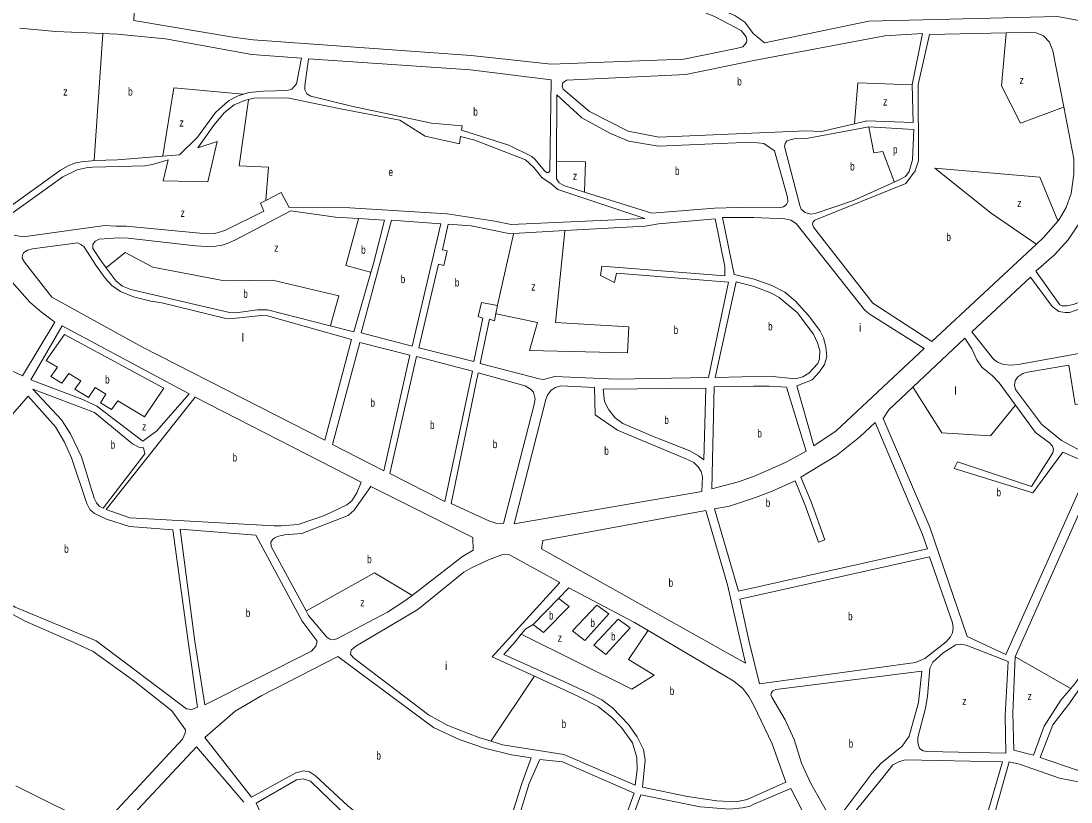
# Model space of a CAD drawing. Extents: x 639657 to 671642, y 222838 to 252123.
# Drawn here: x 647091 to 648393, y 241801 to 242770 of the extents above; entities that cross this region are included whole.
import ezdxf

# ---------------------------------------------------------------- set-up
doc = ezdxf.new("R2010")
doc.units = 0
doc.header["$LTSCALE"] = 4
doc.layers.add('1', color=7, linetype='Continuous', lineweight=13)
doc.layers.add('21', color=7, linetype='Continuous', lineweight=13)
doc.layers.add('7', color=7, linetype='Continuous')

msp = doc.modelspace()

# ---------------------------------------------------------------- linework, layer by layer
at = {"layer": '1'}
for p, q in [((647134.57, 242756.69), (647090.209, 242760.748)), ((648339.65, 242755.58), (648312.78, 242754.994)), ((647699.28, 242517.39), (647864.7, 242524.83))]:
    msp.add_line(p, q, dxfattribs=at)
for points in [[(648475.98, 242756.77), (648376.31, 242775.21), (648142.52, 242769.48), (648013.13, 242742.54), (647999.2, 242754.16), (647988.99, 242768.22), (647976.55, 242776.66), (647885.12, 242815.13), (647816.64, 242839.95), (648199.3, 242913.73), (648230.16, 242918.09), (648262.57, 242919.67), (648282.75, 242919.08), (648368, 242913.27), (648382.38, 242915.24), (648400.83, 242922.59)], [(647367.385, 242679.215), (647373.95, 242681.34), (647392.01, 242682.98), (647421.67, 242683.5), (647427.27, 242685.2), (647432.88, 242691.84), (647439.01, 242723.62), (647377.77, 242728.18), (647270.59, 242747.54), (647210.86, 242753.59), (647193.101, 242754.312), (647134.57, 242756.69)], [(648064.94, 242633.79), (647882.07, 242625.57), (647844.05, 242633.27), (647796.43, 242657.56), (647763.43, 242685.22), (647762.15, 242688.88), (647763.03, 242693.18), (647767.77, 242696.38), (647915.46, 242703.44), (647999.87, 242720.81), (648162.53, 242751.49), (648208.9, 242754.18), (648196.4, 242690.59)], [(648312.78, 242754.994), (648217.71, 242752.92), (648203.49, 242691.25), (648204.16, 242596.56), (648200.12, 242583.88), (648188.35, 242568.18), (648075.53, 242522.81), (648073.61, 242520.66), (648072.76, 242517.87), (648074.05, 242514), (648147.52, 242419.72), (648220.43, 242372.45), (648350.264, 242493.088)], [(648384.189, 242663.305), (648370.84, 242732.89), (648366.52, 242743.4), (648359.2, 242751.33), (648349.96, 242755.17), (648339.65, 242755.58)], [(647267.409, 242602.008), (647288.12, 242603.66), (647310.13, 242625.93), (647332.59, 242656.36), (647348.76, 242670.69), (647360.82, 242677.09), (647367.385, 242679.215)], [(648196.4, 242690.59), (648197.6, 242643.78), (648140.05, 242646), (648124.819, 242642.402)], [(647373.459, 242672.493), (647369.62, 242671.47), (647355.84, 242665.94), (647343.55, 242656.31), (647330.6, 242640.68), (647310.51, 242612.38), (647334.82, 242620.24), (647323.03, 242570.41), (647267.58, 242571.71), (647273.7, 242597.7), (647254.33, 242591.76), (647244.87, 242590.29), (647180.39, 242588.62), (647172.43, 242587.79), (647161.03, 242585.04), (647143.16, 242576.73), (647072.9, 242526.05)], [(647485.43, 242661.3), (647421.86, 242674.69), (647379.94, 242674.22), (647373.459, 242672.493)], [(647755.352, 242596.018), (647755.66, 242678.17), (647786.72, 242649.87), (647822.33, 242630.14), (647845.08, 242620.79), (647881.59, 242614.61), (647996.61, 242619.68), (648012.16, 242617.77), (648025.5, 242609), (648041.54, 242551.5), (648041.98, 242545.49), (648040.49, 242542.26), (648036.84, 242539.46), (648030.41, 242538.16)], [(647864.7, 242524.83), (647756.94, 242560.79), (647748.8, 242567.71), (647737.01, 242575.72), (647727.38, 242588.23), (647716.89, 242597.52), (647654.22, 242622.09), (647636.18, 242626.68), (647635.07, 242617.44), (647592.55, 242626.87), (647561.03, 242647), (647485.43, 242661.3)], [(648376.88, 242521.691), (648378.69, 242523.77), (648387.03, 242538.61), (648393.42, 242555.8), (648396.58, 242579.86), (648396.53, 242598.97), (648384.189, 242663.305)], [(648124.819, 242642.402), (648084.05, 242632.77), (648064.94, 242633.79)], [(648142.43, 242638.71), (648065.39, 242623.92), (648050.15, 242623.88), (648040.92, 242621.07), (648039, 242618.06), (648038.15, 242614.19), (648056.81, 242541.02), (648058.75, 242536.3), (648063.7, 242532.23), (648070.79, 242530.31), (648075.94, 242531.19), (648123.56, 242547.19), (648173.971, 242570.144)], [(648196.65, 242597.83), (648198.48, 242635.41), (648142.43, 242638.71)], [(647182.005, 242596.665), (647211.15, 242597.52), (647267.409, 242602.008)], [(647053.315, 242546.77), (647055.77, 242543.32), (647069.27, 242533.38), (647140.39, 242584.69), (647149.87, 242590.24), (647157.62, 242593.44), (647166.44, 242595.34), (647179.13, 242596.58), (647182.005, 242596.665)], [(647789.901, 242557.716), (647764.48, 242565.7), (647758.48, 242569.17), (647755.27, 242574.13), (647755.352, 242596.018)], [(648173.971, 242570.144), (648181.89, 242573.75), (648187.9, 242576.98), (648192.6, 242583), (648196.65, 242597.83)], [(647394.93, 242547.195), (647413.89, 242557.13), (647423.92, 242538.39), (647499.15, 242538.28), (647619.91, 242530.66), (647678.76, 242521.59), (647699.28, 242517.39)], [(648030.41, 242538.16), (647979.74, 242538.7), (647951.36, 242537.54), (647873.53, 242531.45), (647789.901, 242557.716)], [(647083.13, 242504.08), (647094.3, 242502.1), (647195.58, 242516.11), (647208.91, 242515.19), (647222.02, 242515.57), (647321.71, 242505.92), (647331.59, 242506.31), (647344.07, 242510.13), (647392.31, 242534.01), (647388.26, 242543.7), (647394.93, 242547.195)], [(647510.022, 242524.91), (647481.48, 242526.75), (647425.84, 242534.3), (647356.49, 242498.04), (647347.23, 242493.78), (647340.78, 242491.87), (647332.82, 242490.61), (647322.07, 242490.23), (647307.68, 242491.15), (647224.32, 242500.3), (647212.72, 242500.78), (647188.43, 242499.15), (647183.47, 242496.81), (647180.66, 242492.73), (647180.64, 242487.58), (647191.11, 242471.62), (647196.943, 242463.729)], [(647527.88, 242467.43), (647542.29, 242522.83), (647510.022, 242524.91)], [(647680.101, 242406.972), (647678.27, 242398.19), (647672.26, 242399.94), (647660.85, 242345.16), (647733.85, 242325.92), (647739, 242325.25), (647753.2, 242329.05), (647829.49, 242325.48), (647943.62, 242327.75), (647968.41, 242446.09), (647829.61, 242457.27), (647827.19, 242445.68), (647810.03, 242454.14), (647811.37, 242465.74), (647964.14, 242453.85), (647964.19, 242465.46), (647951.96, 242524.64), (647881.65, 242518.3), (647865.09, 242515.59)], [(647698.17, 242505.88), (647649.51, 242515.7), (647621.15, 242517.76), (647614.15, 242486.19), (647619.73, 242484.66), (647615.57, 242466.62), (647608.92, 242468.15), (647584.85, 242364.63), (647652.7, 242347.56), (647664.1, 242401.48), (647658.3, 242403.22), (647662.24, 242420.83), (647682.21, 242417.09), (647680.101, 242406.972)], [(647698.17, 242505.88), (647702.072, 242506.107), (647765.857, 242509.818), (647865.09, 242515.59)], [(648350.264, 242493.088), (648359.21, 242501.4), (648376.88, 242521.691)], [(648761.04, 242453.22), (648759.63, 242498.73), (648652.51, 242495.04), (648544.39, 242462.35), (648391.23, 242408.3), (648386.08, 242408.28), (648378.13, 242409.55), (648369.74, 242415.97), (648342.81, 242452.19), (648270.21, 242384.17), (648297.13, 242350.53), (648301.87, 242346.68), (648309.6, 242343.9), (648318.84, 242343.07), (648327.64, 242343.95), (648462.19, 242368.11), (648485.81, 242369.46), (648514.57, 242369.53), (648535.83, 242367.65), (648547.304, 242365.892), (648673.204, 242346.603)], [(647005.043, 242370.874), (647093.18, 242329.89), (647133.21, 242396.17), (647116.71, 242408.71), (647102.36, 242421.02), (647080.54, 242446.04), (647064.011, 242474.655)], [(647196.943, 242463.729), (647209.28, 242447.04), (647217.43, 242440.99), (647227.72, 242436.65), (647350.12, 242408.41), (647357.64, 242407.95), (647384.52, 242411.49), (647397.2, 242411.44), (647474.84, 242391.907)], [(647474.84, 242391.907), (647504.12, 242384.54), (647525.2, 242458.079), (647527.88, 242467.43)], [(648324.41, 242293.388), (648304.08, 242320.92), (648295.9, 242329.7), (648282.77, 242340.62), (648276.31, 242349.62), (648270.26, 242363.34), (648261.42, 242376.42), (648197.271, 242315.764)], [(648390.541, 242342.903), (648339.26, 242334.32), (648333.25, 242332.59), (648327.25, 242328.71), (648324.04, 242323.55), (648323.2, 242318.18), (648324.5, 242313.03), (648356.6, 242269.96), (648381.35, 242249.63), (648434.299, 242221.396)], [(648390.541, 242342.903), (648398.521, 242294.274), (648413.2, 242296.372), (648404.192, 242345.188)], [(648197.271, 242315.764), (648167.4, 242287.52), (648160.13, 242276.77), (648218.24, 242142.1), (648264.25, 242006.58)], [(648264.25, 242006.58), (648312.32, 241984.39), (648412.59, 242208.92), (648407.82, 242224.58), (648382.89, 242235.25), (648345.88, 242184.49), (648248.32, 242214.95), (648252.38, 242223.33), (648344.35, 242192.43), (648370.65, 242234.36), (648371.29, 242238.87), (648370.2, 242242.51), (648366.97, 242246.37), (648349.33, 242259.64), (648324.41, 242293.388)], [(648398.97, 241949.45), (648442.64, 242013.16), (648498.51, 242112.54), (648490.22, 242162.1), (648485.03, 242173.68), (648463.52, 242191.44), (648437.5, 242207.48), (648431.48, 242209.39), (648418.21, 242193.05), (648324.1, 241981.38)], [(647576.308, 242057.511), (647638.95, 242105.72), (647652.1, 242113.4), (647651.74, 242129.32), (647525.22, 242192.44), (647504.67, 242163.28), (647497.12, 242156.43), (647439.64, 242134.31), (647418.14, 242132.47), (647409.32, 242130.35), (647406.09, 242128.86)], [(647406.09, 242128.86), (647403.72, 242127.15), (647401.34, 242123.72), (647401.74, 242118.34), (647444.93, 242038.208)], [(647500.81, 241989.47), (647506.43, 241994.43), (647583.42, 242039.94), (647640.37, 242086.14), (647649.2, 242091.26), (647670.96, 242101.7), (647687.75, 242107.65), (647696.13, 242108.04), (647702.57, 242105.01), (647759.59, 242073.57), (647675.41, 241981.36), (647727.859, 241957.32)], [(647757.985, 242053.719), (647770.73, 242066.85), (647852.17, 242023.73), (647868.882, 242013.866)], [(647444.93, 242038.208), (647447.98, 242032.55), (647470.64, 242005.58), (647474.28, 242003.2), (647477.93, 242002.32), (647483.09, 242003.59), (647545.79, 242036.87), (647568.64, 242051.61), (647576.308, 242057.511)], [(647711.654, 242009.265), (647717.2, 242016.12), (647726.46, 242021.24), (647757.985, 242053.719)], [(647053.91, 242048.11), (647096.79, 242025.58), (647156.14, 241999.7), (647180.89, 241987.99), (647232.37, 241950.63), (647278.49, 241914.32), (647295.34, 241890.77), (647294.93, 241886.48), (647291.74, 241879.17), (647189.6, 241769.28), (647085.01, 241821.24)], [(648039.64, 241825.94), (647991.6, 241804.41), (647978.08, 241801.56), (647954.03, 241802.76), (647917.72, 241808.2), (647862.07, 241819.58), (647865.14, 241853.08), (647863.15, 241866.38), (647855.35, 241882.24), (647844.54, 241897.44), (647824.91, 241918.19), (647811.56, 241928.01), (647797.14, 241935.25), (647768.31, 241949.09), (647690.21, 241984.42), (647704.1, 241999.93), (647711.654, 242009.265)], [(647868.882, 242013.866), (647963.87, 241957.8), (647975.06, 241950.97), (647986.27, 241942), (647993.83, 241931.94), (647999.89, 241920.8), (648022.78, 241873.63), (648039.64, 241825.94)], [(647674.183, 241876.769), (647659.11, 241881.47), (647620.61, 241896.13), (647596.72, 241909.56), (647503.64, 241980.04), (647499.97, 241984.75), (647500.81, 241989.47)], [(648324.1, 241981.38), (648321.15, 241912.05), (648322.34, 241865.47), (648346.81, 241859.41), (648359.99, 241895.23), (648380.45, 241927.59), (648392.808, 241942.177), (648398.97, 241949.45)], [(647727.859, 241957.32), (647780.83, 241933.04), (647806.87, 241919.62), (647824.11, 241906.16), (647835.76, 241893.75), (647849.37, 241874.7), (647855.03, 241856.69), (647855.53, 241841.02), (647852.82, 241822.33), (647764.41, 241860.2), (647688.35, 241872.35), (647674.183, 241876.769)], [(647367.55, 241801.031), (647308.96, 241869.79), (647206.39, 241760.11), (647307.32, 241707.06), (647336.119, 241696.742)]]:
    msp.add_lwpolyline(points, dxfattribs=at)
for points in [[(647991.27, 242745.85), (647990.43, 242750.15), (647984.44, 242757.92), (647951.4, 242775.27), (647857.39, 242813.32), (647829.91, 242822.26), (647802.2, 242827.98), (647778.35, 242829.59), (647749.54, 242829.72), (647720.73, 242826.63), (647623.35, 242824.27), (647489.24, 242826.15), (647327.61, 242826.83), (647275.61, 242830.7), (647234.15, 242838.39), (647231.34, 242770.49), (647354.21, 242749.56), (647379.34, 242746.66), (647649.45, 242727.01), (647748.71, 242716.24), (647913.16, 242722.58), (647978.12, 242735.6), (647986.51, 242737.92), (647990.83, 242743.06)], [(647501.13, 242664.03), (647450.88, 242676.71), (647445.95, 242679.53), (647443.17, 242684.27), (647443.19, 242689.43), (647447.82, 242722.73), (647648.52, 242709.39), (647748.64, 242696.9), (647746.93, 242584.06), (647745.42, 242582.13), (647743.05, 242582.14), (647740.48, 242584.08), (647728.93, 242598.11), (647724.64, 242601.78), (647696.32, 242615.88), (647637.5, 242634.63), (647638.38, 242639.79), (647600.35, 242643.18)], [(648480.354, 242638.657), (648556.16, 242636.72), (648558.96, 242635.44), (648560.68, 242633.08), (648602.02, 242506.72), (648604.63, 242495.13), (648600.14, 242489.32), (648596.49, 242487.17), (648525.32, 242464.75), (648395.72, 242418.4), (648388.21, 242416.45), (648382.41, 242416.65), (648379.4, 242417.93), (648349.66, 242459.51), (648372.8, 242479.96), (648389.49, 242498.25), (648403.82, 242519.54), (648412.14, 242539.53), (648420.02, 242564.67), (648421.71, 242575.62)], [(647611.91, 242518.23), (647550.67, 242522.8), (647513.14, 242383), (647576.48, 242366.6)], [(648022.28, 242441.74), (648000.58, 242449.84), (647975.75, 242455.3), (647961.21, 242526.31), (648000.11, 242526.13), (648038.39, 242524.65), (648045.69, 242522.74), (648052.36, 242518.67), (648137.02, 242411.75), (648143.04, 242406.61), (648211.22, 242363.63), (648102.2, 242261.38), (648074.34, 242242.85), (648053.31, 242317.51), (648072.19, 242324.85), (648081.4, 242334.54), (648087.6, 242344), (648090.58, 242353.24), (648089.26, 242365.69), (648086.44, 242376.84), (648081.9, 242386.06), (648067.9, 242404.71), (648051.11, 242422.7), (648038.2, 242433.4)], [(647468.3, 242249.88), (647501.29, 242374.67), (647396.95, 242404.35), (647389.65, 242404.81), (647350.08, 242400.46), (647343.64, 242401.34), (647266.13, 242420.37), (647252.38, 242422.57), (647230.91, 242427.82), (647214.82, 242434.33), (647204.1, 242441.9), (647195.76, 242450.75), (647185.07, 242465.63), (647169.48, 242489.98), (647165.83, 242492.79), (647161.97, 242494.53), (647105.85, 242487.44), (647099.39, 242485.53), (647095.08, 242482.75), (647093.14, 242479.97), (647092.69, 242475.88), (647095.9, 242470.71), (647129.68, 242427.36), (647242.26, 242365.21)], [(648021.88, 242432.29), (648000.249, 242440.664), (647978.08, 242446.48), (647952.01, 242327.71), (648018.88, 242329.2), (648051.79, 242325.88), (648060.58, 242328.47), (648068.09, 242333.22), (648079.22, 242345.27), (648081.35, 242350.85), (648081.75, 242361.16), (648078.94, 242370.81), (648073.97, 242381.54), (648053.5, 242408.32), (648031.56, 242426.73)], [(647300.05, 242307.35), (647142.65, 242391.62), (647103.69, 242324.69), (647168.28, 242300.35), (647185.44, 242292.33), (647242.63, 242248.88), (647259.88, 242261.49)], [(647573.64, 242355.43), (647511.59, 242370.97), (647477.52, 242244.68), (647541.21, 242211.94)], [(647651.14, 242335.53), (647581.58, 242353.89), (647548.51, 242208.68), (647616.7, 242173.98)], [(647716.61, 242317.18), (647658.22, 242333.56), (647624.85, 242171.58), (647671.39, 242150.09), (647680.19, 242147.25), (647689.43, 242146.78), (647727.26, 242292.4), (647729.01, 242301.21), (647726.9, 242309.61), (647723.05, 242313.28)], [(647803.29, 242281.31), (647802.58, 242315.28), (647760.68, 242317.41), (647754.22, 242315.5), (647748.62, 242311.87), (647744.29, 242305.87), (647742.12, 242300.29), (647702.75, 242146.29), (647935.7, 242186.52), (647936.21, 242204.58), (647934.73, 242211.25), (647931.11, 242217.08), (647925.54, 242222.26), (647915.03, 242227.47), (647830.93, 242262.26)], [(647937.81, 242225.43), (647940.34, 242314.65), (647813.1, 242313.09), (647814.97, 242298.03), (647820.08, 242287.47), (647827.99, 242277.54), (647837.63, 242270.62), (647874.32, 242254.97), (647920.66, 242236.69), (647931.17, 242230.62)], [(648018.96, 242316.78), (647999.46, 242317.17), (647950.67, 242316.11), (647947.75, 242189.69), (647981.1, 242198.35), (648001.45, 242205.73), (648040.03, 242222.8), (648064.69, 242236.17), (648040.65, 242315.54)], [(647310.46, 241918.95), (647298.5, 242000.26), (647279.76, 242138.84), (647226.05, 242143.14), (647197.29, 242152.07), (647182.5, 242159.01), (647176.93, 242164.2), (647173.09, 242171.31), (647154, 242227.94), (647145.27, 242247.54), (647134.18, 242266.73), (647100.38, 242304.49), (646967.34, 242152.1), (646991.09, 242129.22), (647017.81, 242096), (647061.68, 242056.47), (647084.4, 242042.83), (647184.75, 242001.31), (647296.73, 241916.75), (647303.17, 241916.13)], [(647182.39, 242284.17), (647106.01, 242313.28), (647141.52, 242275.3), (647152.62, 242258.05), (647166.47, 242229.4), (647182.15, 242178.15), (647184.92, 242172.12), (647188.55, 242168.02), (647193.49, 242165.64), (647244.93, 242233.17), (647243.24, 242240.7), (647237.66, 242241.15), (647229.72, 242245.27)], [(647513.21, 242198.08), (647307.56, 242303.45), (647196.92, 242164.12), (647226.53, 242153.89), (647234.05, 242153.22), (647405.29, 242143.7), (647414.11, 242143.66), (647434.96, 242145.51), (647467.89, 242156.56), (647495.46, 242169.77), (647501.5, 242174.91), (647507.99, 242184.77)], [(648022.52, 242186.91), (648002.03, 242179.07), (647970, 242168.3), (647951.29, 242164.73), (647980.92, 242062.93), (648215.09, 242115.05), (648209.03, 242132.85), (648150.27, 242271.81), (648131.42, 242254.16), (648102.28, 242230.9), (648058.12, 242204.17), (648070.87, 242173.72), (648087.95, 242126.54), (648080.23, 242123.51), (648063.36, 242170.05), (648051.26, 242199.65)], [(647967.19, 242070.68), (647989.8, 241973.51), (647736.57, 242115.39), (647738.55, 242125.71), (647940.53, 242162.85)], [(647456.77, 241994.67), (647458.567, 242000.923), (647440, 242025.71), (647382.46, 242132.18), (647288.79, 242139.66), (647306.87, 242000.3), (647319.25, 241921.78), (647451.65, 241988.2)], [(648538.87, 242000), (648581.7, 242074.75), (648506.46, 242110.2), (648471.4, 242051.3), (648451.98, 242012.2), (648391.62, 241924.35), (648370.73, 241897.13), (648354.75, 241856.6), (648400.68, 241840.83), (648428.59, 241840.77), (648447.5, 241843.95)], [(648211.77, 241979.05), (648238.359, 242000.01), (648243.72, 242006.3), (648246.07, 242011.24), (648246.91, 242017.47), (648246.46, 242023.48), (648217.91, 242105.4), (647982.56, 242052.75), (647994.15, 242000.02), (648006.81, 241948.03), (648200.59, 241974.35)], [(648215.017, 241863.991), (648312.24, 241861.84), (648311.7, 241908.64), (648315.06, 241975.6), (648263.13, 241995.68), (648256.26, 241996.98), (648250.24, 241996.13), (648234.55, 241986.3), (648221.85, 241974.73), (648218.19, 241967.44), (648215.32, 241932.03), (648212.93, 241917.87), (648203.19, 241881.19), (648203.17, 241874.53), (648205.52, 241867.66), (648210.03, 241864.86)], [(647389.84, 241933.22), (647484.31, 241981.89), (647602.8, 241893.7), (647634.86, 241879.01), (647666.04, 241867.97), (647699.57, 241859.73), (647724.06, 241856.18), (647712.18, 241824.14), (647694.82, 241769.33), (647678.61, 241742.86), (647667.28, 241732.73), (647653.78, 241726.88), (647634.67, 241725.94), (647585.88, 241737.35), (647520.44, 241777.02), (647496.52, 241796.46), (647456.63, 241833.88), (647449.09, 241838.78), (647441.79, 241839.83), (647432.35, 241837.43), (647377.31, 241807.16), (647319.43, 241881.42), (647356.86, 241913.77)], [(648204.14, 241924.76), (648208.08, 241963.6), (648027.43, 241940.81), (648023.35, 241939.11), (648021.84, 241937.18), (648020.97, 241934.39), (648022.26, 241931.17), (648038.95, 241903.22), (648050.06, 241878.73), (648059.24, 241849.51), (648070.35, 241825.23), (648099.02, 241773.85), (648146.4, 241836.66), (648158.02, 241849.3), (648184.05, 241870.49), (648192.45, 241883.14)], [(647721.41, 241824.18), (647734.517, 241854.174), (647762.73, 241851.18), (647851.79, 241812.24), (647803.85, 241679.8), (647751.82, 241695.27), (647673.34, 241722.45), (647688.93, 241741.4), (647703.21, 241765.28)], [(648159.92, 241831.69), (648105.44, 241764.82), (648174.41, 241677.5), (648203.14, 241653.39), (648290.62, 241789.98), (648308.35, 241851.12), (648187.88, 241853.74), (648180.36, 241851.61), (648172.41, 241847.33)], [(648569.43, 241715.31), (648594.07, 241794.04), (648469.37, 241827.8), (648450.26, 241828.7), (648420.19, 241825.12), (648404.51, 241826.01), (648378.97, 241830.79), (648329.18, 241848.07), (648316.3, 241851.1), (648298.99, 241789.53)], [(647513.81, 241769.7), (647557.09, 241743.25), (647476.78, 241646.54), (647419.79, 241667.57), (647423.74, 241696.78), (647419.99, 241718.66), (647382.92, 241799.67), (647433.04, 241828.63), (647441.4, 241830.17), (647450.22, 241827.2), (647486.88, 241792.13)], [(647999.78, 241798.43), (648045.64, 241817.98), (648066.17, 241778.86), (648069.38, 241770.48), (648070.65, 241762.75), (648067.4, 241750.73), (648050.14, 241712.55), (647924.77, 241669.97), (647909.96, 241667.76), (647832.43, 241673.9), (647812.01, 241678.33), (647859.74, 241810.34), (647933.24, 241795.38), (647969.75, 241792.3), (647986.06, 241794.08), (647995.28, 241796.05)]]:
    msp.add_lwpolyline(points, close=True, dxfattribs=at)
at = {"layer": '21'}
for points in [[(647193.101, 242754.312), (647193.066, 242753.812), (647182.04, 242597.164), (647182.005, 242596.665)], [(648312.78, 242754.994), (648312.736, 242754.494), (648306.951, 242689.4), (648330.718, 242643.244), (648383.689, 242663.117), (648384.189, 242663.305)], [(648124.819, 242642.402), (648124.861, 242642.902), (648129.054, 242693.244), (648195.9, 242690.61), (648196.4, 242690.59)], [(647267.409, 242602.008), (647267.488, 242602.508), (647280.815, 242686.95), (647366.885, 242679.26), (647367.385, 242679.215)], [(647373.459, 242672.493), (647373.389, 242671.993), (647361.9, 242590.094), (647398.248, 242588.695), (647394.97, 242547.695), (647394.93, 242547.195)], [(648142.43, 242638.71), (648142.526, 242638.21), (648148.626, 242606.526), (648159.81, 242607.925), (648173.784, 242570.644), (648173.971, 242570.144)], [(647755.352, 242596.018), (647755.852, 242596.009), (647791.436, 242595.337), (647789.921, 242558.216), (647789.901, 242557.716)], [(648350.264, 242493.088), (648349.764, 242493.43), (648294.369, 242531.35), (648224.469, 242587.297), (648354.484, 242576.107), (648376.674, 242522.191), (648376.88, 242521.691)], [(647510.022, 242524.91), (647509.885, 242524.41), (647494.011, 242466.659), (647524.7, 242458.217), (647525.2, 242458.079)], [(647680.101, 242406.972), (647680.601, 242406.866), (647731.672, 242396.027), (647721.886, 242361.06), (647843.512, 242358.263), (647844.91, 242390.432), (647754.04, 242396.027), (647765.805, 242509.317), (647765.857, 242509.818)], [(647682.21, 242417.09), (647682.322, 242417.59), (647701.96, 242505.607), (647702.072, 242506.107)], [(647196.943, 242463.729), (647197.443, 242464.129), (647220.701, 242482.744), (647254.952, 242464.561), (647343.725, 242447.777), (647403.141, 242448.477), (647485.623, 242428.895), (647474.986, 242392.407), (647474.84, 242391.907)], [(648324.41, 242293.388), (648324, 242292.888), (648293.323, 242255.459), (648233.209, 242258.956), (648197.587, 242315.264), (648197.271, 242315.764)], [(647576.308, 242057.511), (647575.808, 242057.813), (647529.669, 242085.684), (647445.43, 242038.488), (647444.93, 242038.208)], [(647726.46, 242021.24), (647726.96, 242020.854), (647739.33, 242011.307), (647771.072, 242043.9), (647758.485, 242053.344), (647757.985, 242053.719)], [(647711.654, 242009.265), (647712.154, 242009.016), (647848.755, 241941.108), (647876.32, 241958.658), (647844.579, 241977.879), (647868.544, 242013.366), (647868.882, 242013.866)], [(648324.1, 241981.38), (648324.6, 241981.095), (648392.308, 241942.462), (648392.808, 241942.177)], [(647727.859, 241957.32), (647727.526, 241956.82), (647674.516, 241877.269), (647674.183, 241876.769)]]:
    msp.add_lwpolyline(points, dxfattribs=at)
for points in [[(647145.2, 242381.169), (647268.637, 242314.671), (647244.413, 242278.736), (647211.418, 242298.793), (647203.483, 242287.929), (647190.118, 242296.286), (647196.8, 242307.15), (647183.435, 242315.507), (647175.082, 242302.972), (647158.376, 242313.418), (647165.476, 242323.447), (647150.858, 242332.639), (647142.088, 242320.522), (647128.305, 242328.879), (647136.658, 242340.578), (647122.458, 242348.935)], [(647805.367, 242045.48), (647775.248, 242013.397), (647790.283, 242001.697), (647820.354, 242034.707)], [(647831.679, 242027.93), (647801.56, 241995.847), (647816.595, 241984.147), (647846.666, 242017.157)]]:
    msp.add_lwpolyline(points, close=True, dxfattribs=at)

# ---------------------------------------------------------------- texts
at = {"layer": '7'}
for s, width, p in [('b', 0.75, (647979.386, 242689.875)), ('z', 0.8, (648329.302, 242691.527)), ('z', 0.8, (647143.891, 242677.292)), ('b', 0.75, (647224.276, 242677.292)), ('z', 0.8, (648160.142, 242664.953)), ('b', 0.75, (647652.149, 242652.43)), ('z', 0.8, (647287.885, 242638.829)), ('p', 0.75, (648172.49, 242605.491)), ('b', 0.75, (647902.211, 242578.935)), ('b', 0.75, (648119.366, 242584.51)), ('e', 0.75, (647547.118, 242577.536)), ('z', 0.8, (647775.691, 242572.64)), ('z', 0.8, (648326.506, 242539.072)), ('z', 0.8, (647289.284, 242526.935)), ('b', 0.75, (648238.714, 242496.879)), ('z', 0.8, (647405.318, 242483.576)), ('b', 0.75, (647513.142, 242481.099)), ('b', 0.75, (647562.216, 242444.7)), ('b', 0.75, (647629.321, 242440.504)), ('b', 0.75, (647367.05, 242426.551)), ('z', 0.8, (647723.965, 242435.57)), ('b', 0.75, (647900.534, 242381.76)), ('b', 0.75, (648017.634, 242386.18)), ('b', 0.75, (647195.714, 242320.25)), ('b', 0.75, (647524.66, 242291.455)), ('b', 0.75, (647889.032, 242270.04)), ('z', 0.8, (647241.488, 242262.022)), ('b', 0.75, (647598.485, 242263.935)), ('b', 0.75, (648004.342, 242253.43)), ('b', 0.75, (647202.563, 242239.46)), ('b', 0.75, (647676.336, 242240.17)), ('b', 0.75, (647814.533, 242231.85)), ('b', 0.75, (647353.804, 242223.555)), ('b', 0.75, (648300.784, 242180.405)), ('b', 0.75, (648014.729, 242167.37)), ('b', 0.75, (647144.959, 242110.31)), ('b', 0.75, (647520.575, 242097.38)), ('b', 0.75, (647894.301, 242068.18)), ('b', 0.75, (647370.108, 242030.72)), ('z', 0.8, (647512.079, 242043.844)), ('b', 0.75, (647746.012, 242027.604)), ('b', 0.75, (647797.384, 242018.411)), ('b', 0.75, (648116.808, 242026.715)), ('z', 0.8, (647756.824, 241999.97)), ('b', 0.75, (647822.86, 242001.697)), ('b', 0.75, (647895.675, 241934.205)), ('z', 0.8, (648258.232, 241921.463)), ('z', 0.8, (648339.317, 241927.757)), ('b', 0.75, (647761.753, 241893.193)), ('b', 0.75, (648117.543, 241868.725)), ('b', 0.75, (647532.044, 241853.915))]:
    msp.add_text(s, height=10, dxfattribs=dict(at, width=width)).set_placement(p)
for s, p in [('i', (648130.308, 242384.58)), ('l', (647365.114, 242372.205)), ('l', (648248.359, 242306.286)), ('i', (647616.979, 241965.185))]:
    msp.add_text(s, height=10, dxfattribs=at).set_placement(p)

doc.saveas('drawing.dxf')
